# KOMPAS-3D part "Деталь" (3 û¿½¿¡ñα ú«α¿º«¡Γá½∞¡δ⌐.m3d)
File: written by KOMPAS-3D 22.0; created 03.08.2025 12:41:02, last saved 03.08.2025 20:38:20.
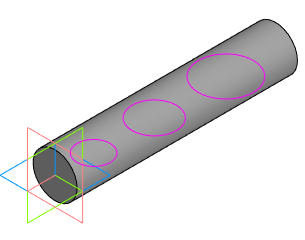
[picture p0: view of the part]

Document properties: Автор: user; Полное имя файла: G:\08 03 воскресенье\2025 НГ Лаб работы\Лаб 3 Взаимное пересечение\3 Цилиндр горизонтальный.m3d

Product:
- Part/product: Деталь
    Масса: 1.974428

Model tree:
1. Эскиз:1
2. Элемент выдавливания:1
     Расстояние 2 = 200
3. Эскиз:2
